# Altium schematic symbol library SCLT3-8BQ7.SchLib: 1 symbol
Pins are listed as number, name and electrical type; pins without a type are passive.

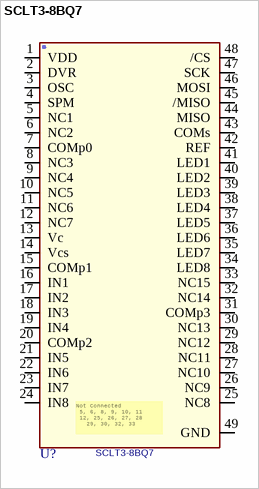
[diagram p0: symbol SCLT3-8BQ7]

## SCLT3-8BQ7
designator U?
footprint ST_QFN50P700X700X100-49L (Footprint not found)
pins: 1 VDD, 2 DVR, 3 OSC, 4 SPM, 5 NC1, 6 NC2, 7 COMp0, 8 NC3, 9 NC4, 10 NC5, 11 NC6, 12 NC7, 13 Vc, 14 Vcs, 15 COMp1, 16 IN1, 17 IN2, 18 IN3, 19 IN4, 20 COMp2, 21 IN5, 22 IN6, 23 IN7, 24 IN8, 25 NC8, 26 NC9, 27 NC10, 28 NC11, 29 NC12, 30 NC13, 31 COMp3, 32 NC14, 33 NC15, 34 LED8, 35 LED7, 36 LED6, 37 LED5, 38 LED4, 39 LED3, 40 LED2, 41 LED1, 42 REF, 43 COMs, 44 MISO, 45 /MISO, 46 MOSI, 47 SCK, 48 /CS, 49 GND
